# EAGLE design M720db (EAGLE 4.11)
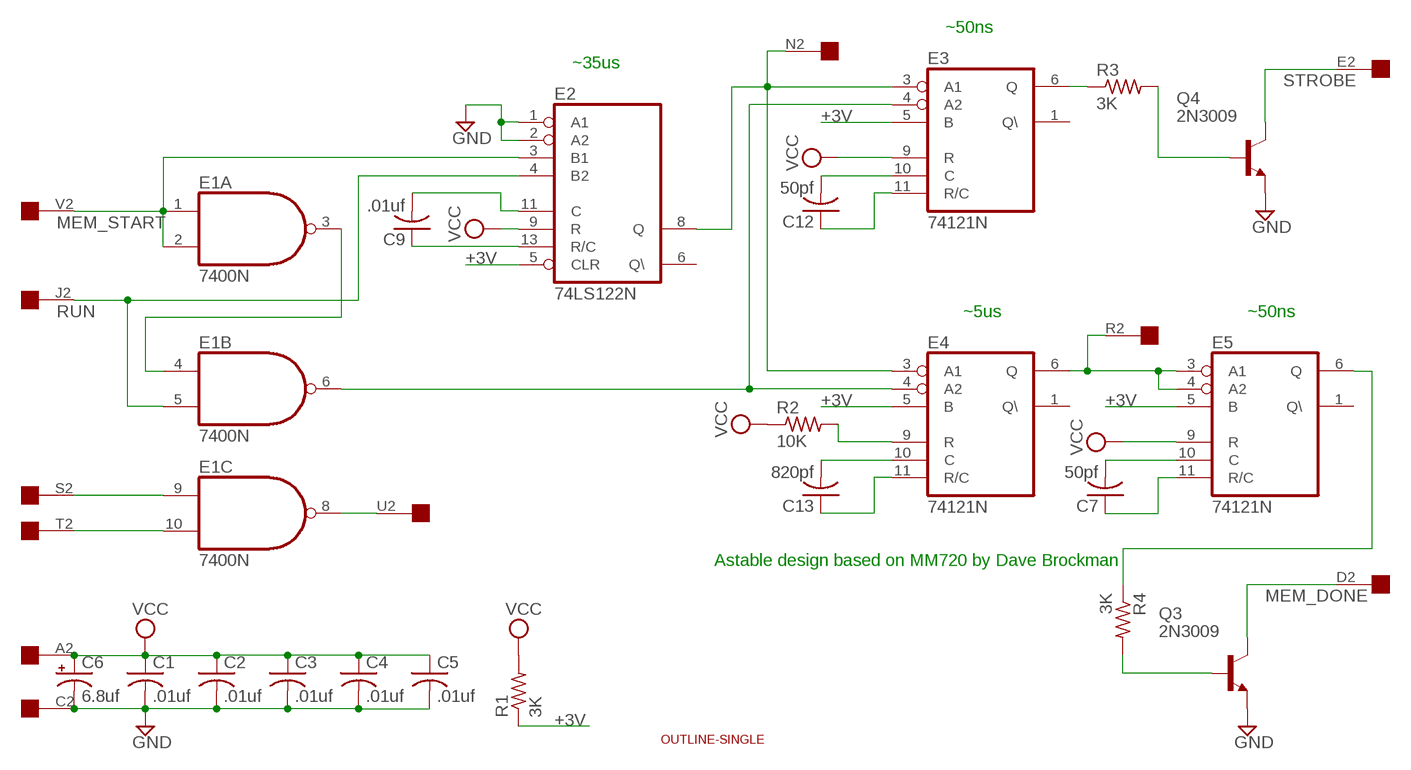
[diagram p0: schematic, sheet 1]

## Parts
C1  .01uf  C-US050-025X075  [C050-025X075]
C2  .01uf  C-US050-025X075  [C050-025X075]
C3  .01uf  C-US050-025X075  [C050-025X075]
C4  .01uf  C-US050-025X075  [C050-025X075]
C5  .01uf  C-US050-025X075  [C050-025X075]
C6  6.8uf  CPOL-USE15-5AXIAL  [E15-5]
C7  50pf  C-US050-025X075  [C050-025X075]
C9  .01uf  C-US050-025X075  [C050-025X075]
C12  50pf  C-US050-025X075  [C050-025X075]
C13  820pf  C-US050-025X075  [C050-025X075]
E1  7400N  [DIL14]
E2  74LS122N  [DIL14]
E3  74121N  [DIL14]
E4  74121N  [DIL14]
E5  74121N  [DIL14]
Q3  2N3009  2N2405  [TO5]
Q4  2N3009  2N2405  [TO5]
R1  3K  R-US_0207/10  [0207/10]
R2  10K  R-US_0207/10  [0207/10]
R3  3K  R-US_0207/10  [0207/10]
R4  3K  R-US_0207/10  [0207/10]
U$1  OUTLINE-SINGLE  [SINGLE]
U$3  EDGE-1  [EDGE-CON1]

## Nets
+3V: E2.5(CLR) E3.5(B) E4.5(B) E5.5(B) R1.1
GND [supply]: C1.2 C2.2 C3.2 C4.2 C5.2 C6.- E2.1(A1) E2.2(A2) Q3.1(E) Q4.1(E) U$3.C2
MEM_DONE: Q3.3(C) U$3.D2
MEM_START: E1.1(A:I0) E1.2(A:I1) E2.3(B1) U$3.V2
N$1: E1.3(A:O) E1.4(B:I0)
N$2: E1.6(B:O) E3.4(A2) E4.4(A2)
N$3: E2.8(Q) E3.3(A1) E4.3(A1) U$3.N2
N$4: C9.2 E2.11(C)
N$5: E1.9(C:I0) U$3.S2
N$6: E1.10(C:I1) U$3.T2
N$7: E1.8(C:O) U$3.U2
N$11: E4.6(Q) E5.3(A1) E5.4(A2) U$3.R2
N$12: C7.2 E5.10(C)
N$13: C7.1 E5.11(R/C)
N$14: E3.6(Q) R3.1
N$15: Q4.2(B) R3.2
N$16: E5.6(Q) R4.1
N$20: C9.1 E2.13(R/C)
N$24: Q3.2(B) R4.2
N$25: C12.1 E3.11(R/C)
N$26: C12.2 E3.10(C)
N$27: C13.1 E4.11(R/C)
N$28: C13.2 E4.10(C)
N$29: E4.9(R) R2.2
RUN: E1.5(B:I1) E2.4(B2) U$3.J2
STROBE: Q4.3(C) U$3.E2
VCC [supply]: C1.1 C2.1 C3.1 C4.1 C5.1 C6.+ E2.9(R) E3.9(R) E5.9(R) R1.2 R2.1 U$3.A2
Unconnected: E1.11(D:O) E1.12(D:I0) E1.13(D:I1) E2.6(Q\) E3.1(Q\) E4.1(Q\) E5.1(Q\) U$3.B2 U$3.F2 U$3.H2 U$3.K2 U$3.L2 U$3.M2 U$3.P2

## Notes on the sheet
- ~50ns
- ~35us
- ~5us | ~50ns
- Astable design based on MM720 by Dave Brockman

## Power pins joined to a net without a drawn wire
GND: E1.7(P:GND) E2.7(GND) E3.7(GND) E4.7(GND) E5.7(GND)
VCC: E1.14(P:VCC) E2.14(VCC) E3.14(VCC) E4.14(VCC) E5.14(VCC)

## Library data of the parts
C1-C5 C7 C9 C12 C13 = rcl:C-US: CAPACITOR, American symbol
C6 = rcl:CPOL-US: POLARIZED CAPACITOR, American symbol
E1 = 74xx-us:74*00: Quad 2-input NAND gate
E2 = 74xx-us:74*122: Retriggerable monostable MULTIVIBRATOR
E3-E5 = 74xx-us:74*121: Monostable MULTIVIBRATOR, schmitt trigger inputs
Q3 Q4 = transistor:2N2405: NPN TRANSISTOR
R1-R4 = rcl:R-US_: RESISTOR, American symbol
U$1 = dec-con:OUTLINE-*: Board outlines for DEC boards.
U$3 = dec-con:EDGE-1: Single-Sided DEC Edge Connector -- (side 2)

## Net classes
1 supply: width 0.762 mm, drill 0.508 mm

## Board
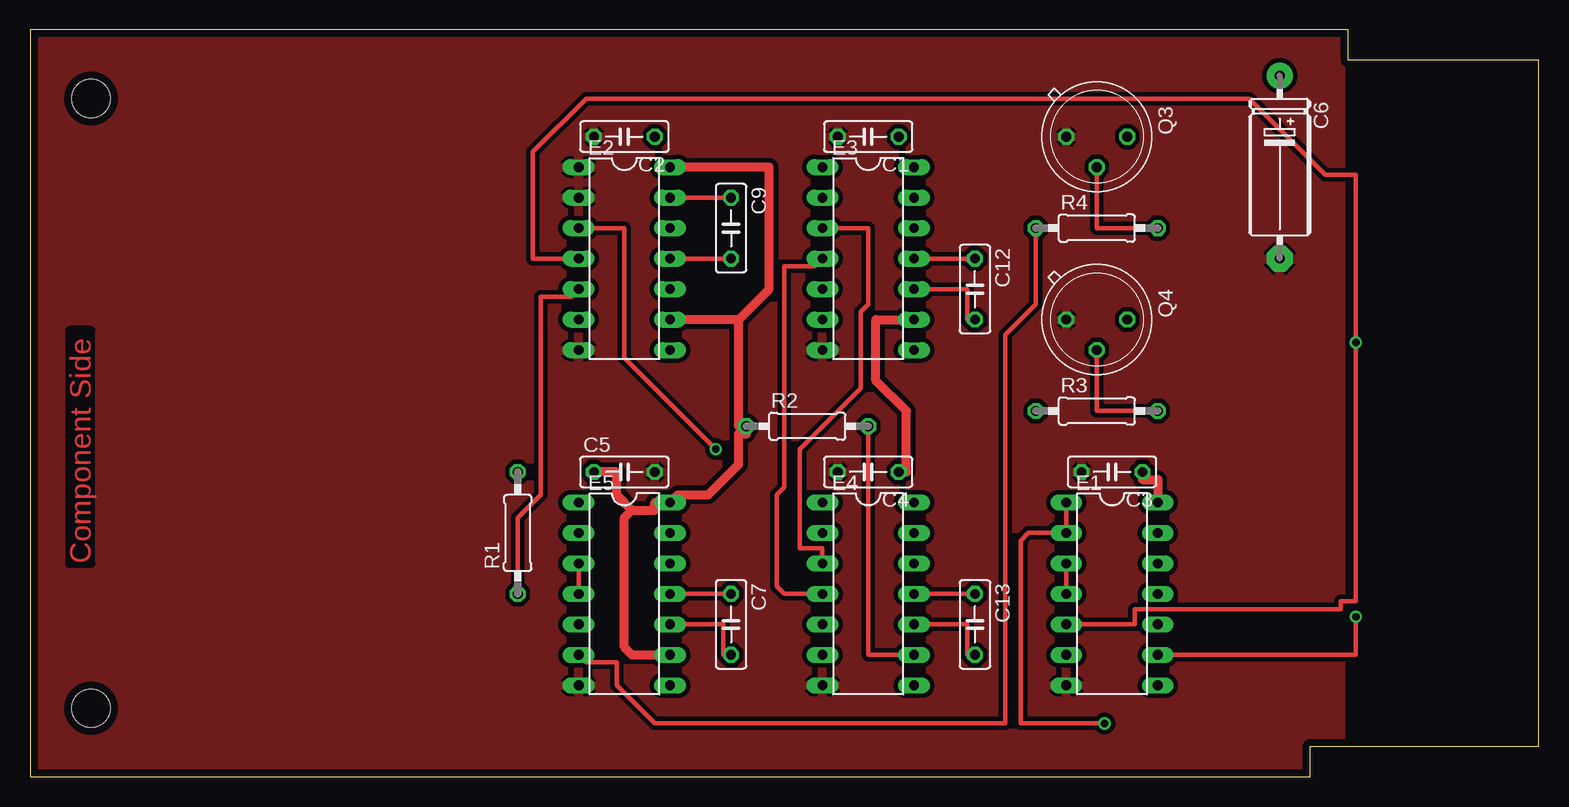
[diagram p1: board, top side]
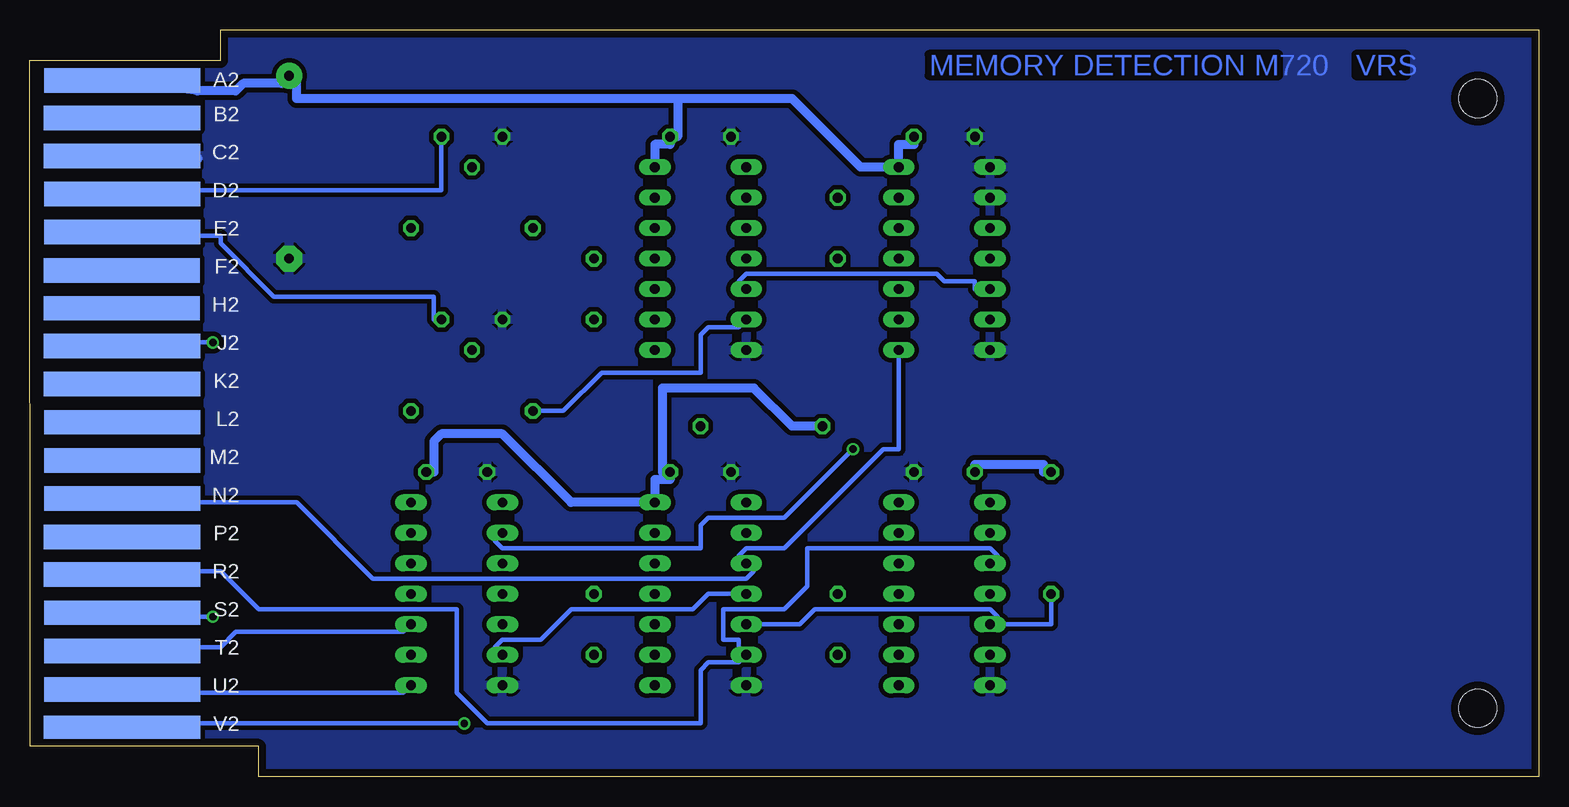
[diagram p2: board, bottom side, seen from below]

Size 125.73 x 62.23 mm. Coordinates in mm from the lower left corner, seen from the top.
Copper layers (1*16): Top 0.035mm / dielectric 1.5mm / Bottom 0.035mm
Design rules "15mils": minimum track width 15mil, minimum drill 24mil, track to track 15mil, track to pad 10mil, pad to pad 10mil, via to via 10mil, smd to smd 10mil, copper to edge 25mil, drill to drill 10mil, minimum pad ring 10mil, minimum via ring 8mil, stop-mask expansion 0mil, vias tented up to drill 0mil, thermal gap 10mil

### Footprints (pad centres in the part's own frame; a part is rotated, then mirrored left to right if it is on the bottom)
C050-025X075 = drill 0.813 octagon: 1 -2.54,0; 2 2.54,0
E15-5 = drill 0.813 pad 2.159 round: + -7.62,0 | drill 0.813 pad 2.159 octagon: - 7.62,0
DIL14 = drill 0.813 long: 1 -7.62,-3.81; 2 -5.08,-3.81; 3 -2.54,-3.81; 4 0,-3.81; 5 2.54,-3.81; 6 5.08,-3.81; 7 7.62,-3.81; 8 7.62,3.81; 9 5.08,3.81; 10 2.54,3.81; 11 0,3.81; 12 -2.54,3.81; 13 -5.08,3.81; 14 -7.62,3.81
TO5 = drill 0.813 octagon: 1 0,-2.54; 2 2.54,0; 3 0,2.54
0207/10 = drill 0.813 octagon: 1 -5.08,0; 2 5.08,0
SINGLE = hole 3.175: 120.65,56.515; 120.65,5.715
EDGE-CON1 = smd 13.017 x 2.032 bottom: A2 7.69,4.194; B2 7.668,7.328; C2 7.668,10.49; D2 7.693,13.665; E2 7.693,16.84; F2 7.642,20.041; H2 7.642,23.19; J2 7.668,26.34; K2 7.668,29.515; L2 7.693,32.69; M2 7.693,35.89; N2 7.693,39.04; P2 7.668,42.24; R2 7.668,45.39; S2 7.693,48.565; T2 7.693,51.74; U2 7.693,54.966 | smd 13.017 x 1.905 bottom: V2 7.668,58.102

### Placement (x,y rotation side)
C1  69.85,53.34 180 top
C2  49.53,53.34 180 top
C3  90.17,25.4 180 top
C4  69.85,25.4 180 top
C5  49.53,25.4 0 top
C6  104.14,50.8 270 top
C7  58.42,12.7 270 top
C9  58.42,45.72 270 top
C12  78.74,40.64 270 top
C13  78.74,12.7 270 top
E1  90.17,15.24 270 top
E2  49.53,43.18 270 top
E3  69.85,43.18 270 top
E4  69.85,15.24 270 top
E5  49.53,15.24 270 top
Q3  88.9,53.34 270 top
Q4  88.9,38.1 270 top
R1  40.64,20.32 90 top
R2  64.77,29.21 0 top
R3  88.9,30.48 0 top
R4  88.9,45.72 0 top
U$1  125.73,62.23 180 top
U$3  125.73,62.23 180 top

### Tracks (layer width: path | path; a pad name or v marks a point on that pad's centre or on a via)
+3V
  Top 0.381: E2.5 45.09,40.01 42.55,40.01 42.55,23.5 40.64,21.59 R1.1
  Bottom 0.381: E2.5 46.99,40.64 46.99,41.27 49.53,41.27 50.16,41.91 66.04,41.91 66.67,41.27 E3.5 | R1.1 40.64,12.7 E5.5 45.09,13.34 45.72,13.97 60.33,13.97 61.59,12.7 E4.5
GND
  Bottom 0.762: U$3.C2 111.76,51.44 111.76,51.61
  pour Bottom: 0,62.23 111.76,62.23 111.76,0 0,0
  pour Top: 0,62.23 109.22,62.23 109.22,0 0,0
MEM_DONE
  Bottom 0.381: Q3.3 91.44,48.9 111.76,48.9 U$3.D2
MEM_START  (via drill 0.61)
  Top 0.381: E1.1 E1.2 83.19,20.32 82.55,19.68 82.55,4.45 v89.53,4.45 | v57.15,27.3 49.53,34.92 49.53,45.72 E2.3
  Bottom 0.381: v57.15,27.3 62.87,21.59 69.22,21.59 69.85,20.95 69.85,19.05 86.36,19.05 87,19.68 E1.2 | v89.53,4.45 111.76,4.45 U$3.V2
N$1
  Top 0.381: E1.4 E1.3
N$2
  Top 0.381: E3.4 65.41,42.55 62.87,42.55 62.87,24.13 62.23,23.5 62.23,15.88 62.87,15.24 E4.4
  Bottom 0.381: E4.4 69.22,15.24 70.48,13.97 80.64,13.97 83.19,11.43 86.36,11.43 87,10.79 E1.6
N$3
  Top 0.381: E3.3 69.85,45.72 69.85,39.37 69.22,38.73 69.22,32.38 64.14,27.3 64.14,19.05 66.04,19.05 E4.3
  Bottom 0.381: E2.8 53.34,27.3 54.61,27.3 62.87,19.05 66.04,19.05 66.67,18.41 E4.3 65.41,17.14 66.04,16.51 97.16,16.51 103.5,22.86 111.76,22.86 U$3.N2
N$4
  Top 0.381: E2.11 C9.2
N$5  (via drill 0.61)
  Top 0.381: v110.49,13.34 110.49,10.16 E1.9
  Bottom 0.381: v110.49,13.34 111.76,13.34 U$3.S2
N$6
  Bottom 0.381: E1.10 94.61,12.06 108.58,12.06 109.86,10.79 111.76,10.79 U$3.T2
N$7
  Bottom 0.381: E1.8 94.61,6.99 111.76,6.99 U$3.U2
N$11
  Top 0.381: E5.4 E5.3
  Bottom 0.381: E5.3 45.09,18.41 45.72,19.05 60.96,19.05 60.96,15.88 62.87,13.97 67.94,13.97 67.94,11.43 66.67,11.43 66.67,10.79 E4.6 66.67,9.53 69.22,9.53 69.85,8.89 69.85,4.45 87.63,4.45 90.17,6.99 90.17,13.97 106.68,13.97 109.86,17.14 111.76,17.14 U$3.R2
N$12
  Top 0.381: E5.10 57.78,12.7 57.78,10.16 C7.2
N$13
  Top 0.381: E5.11 C7.1
N$14
  Bottom 0.381: E3.6 66.67,37.47 69.22,37.47 69.85,36.83 69.85,33.66 78.11,33.66 81.28,30.48 R3.1
N$15
  Top 0.381: R3.2 88.9,30.48 Q4.2
N$16
  Top 0.381: E5.6 46.35,9.53 48.9,9.53 48.9,7.62 52.07,4.45 81.28,4.45 81.28,36.83 83.82,39.37 R4.1
N$20
  Top 0.381: E2.13 C9.1
N$24
  Top 0.381: R4.2 88.9,45.72 Q3.2
N$25
  Top 0.381: E3.11 C12.1
N$26
  Top 0.381: E3.10 78.11,40.64 78.11,38.1 C12.2
N$27
  Top 0.381: E4.11 C13.1
N$28
  Top 0.381: E4.10 78.11,12.7 78.11,10.16 C13.2
N$29
  Top 0.381: E4.9 69.85,10.16 R2.2
RUN  (via drill 0.61)
  Top 0.381: E1.5 92.08,12.7 92.08,13.97 109.22,13.97 109.22,14.61 110.49,14.61 v110.49,36.2 110.49,50.16 107.95,50.16 101.6,56.52 46.35,56.52 41.91,52.07 41.91,43.18 E2.4
  Bottom 0.381: v110.49,36.2 111.76,36.2 U$3.J2
STROBE
  Bottom 0.381: Q4.3 92.08,38.1 92.08,40.01 105.41,40.01 109.86,44.45 109.86,45.09 111.76,45.09 U$3.E2
VCC
  Top 0.762: C3.1 92.71,24.77 93.98,24.77 E1.14 | E3.9 70.48,38.1 70.48,33.02 73.03,30.48 73.03,25.4 C4.1 | 50.16,22.23 49.53,21.59 49.53,10.79 50.16,10.16 E5.9 | 50.16,22.23 52.07,22.23 52.07,22.86 E5.14 53.98,23.5 56.52,23.5 59.05,26.04 59.05,28.57 59.69,28.57 R2.1 59.05,29.21 59.05,38.1 | 59.05,38.1 E2.9 | 59.05,38.1 61.59,40.64 61.59,50.8 E2.14 | 50.16,22.23 48.9,23.5 48.9,25.4 C5.1
  Bottom 0.762: U$3.A2 111.76,57.15 108.58,57.15 107.95,57.78 104.78,57.78 C6.+ 103.5,57.78 103.5,56.52 71.75,56.52 | C3.1 92.08,25.4 92.08,27.94 91.44,28.57 86.36,28.57 80.64,22.86 E4.14 73.66,24.77 72.39,24.77 C4.1 73.03,25.4 73.03,32.38 65.41,32.38 62.23,29.21 R2.1 | R1.2 41.27,25.4 41.27,26.04 46.99,26.04 C5.1 | E3.14 73.66,52.7 72.39,52.7 C1.1 71.75,53.34 71.75,56.52 | C2.1 52.07,52.7 53.34,52.7 E2.14 56.52,50.8 62.23,56.52 71.75,56.52

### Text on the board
Top: Component Side
Bottom: VRS | MEMORY DETECTION M720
